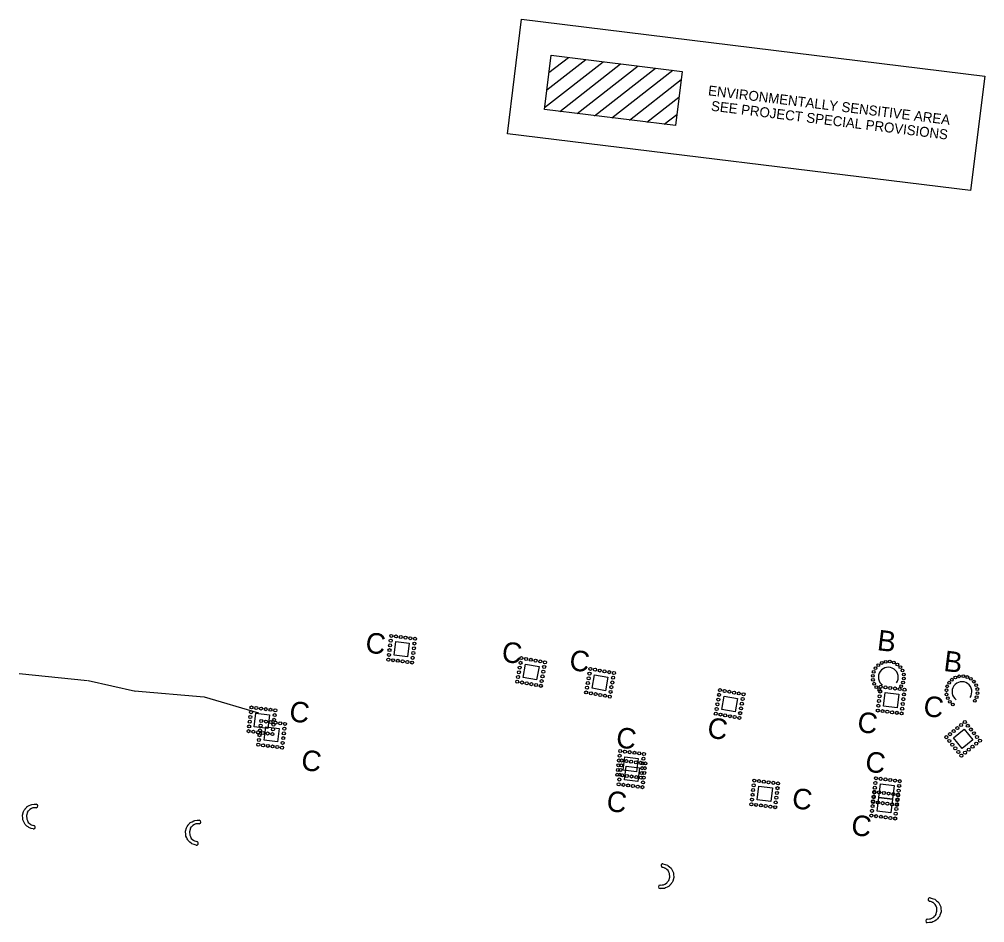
# Model space of a CAD drawing. Extents: x 2470000 to 2520000, y 340000 to 380000.
# Drawn here: x 2481867 to 2482573, y 365982 to 366642 of the extents above; entities that cross this region are included whole.
import ezdxf

# ---------------------------------------------------------------- set-up
doc = ezdxf.new("R2010")
doc.units = 0
for name, color, linetype in [('Environmentally Sensitive Area Note CG CELL', 7, 'Continuous'), ('Label B Final CELL', 7, 'Continuous'), ('Label C CG CELL', 7, 'Continuous'), ('Prop Guardrail', 7, 'Continuous'), ('Prop Guardrail Anchor Unit CELL', 7, 'Continuous'), ('Prop Structure Anchor Unit CELL', 7, 'Continuous'), ('Rock Inlet Sediment Trap Type C CG CELL', 7, 'Continuous'), ('Rock Pipe Inlet Sediment Trap Type B Final CELL', 7, 'Continuous'), ('Scratch_Level_5', 7, 'Continuous'), ('Sheet Data Field CELL', 7, 'Continuous'), ('Wattle Both CELL', 7, 'Continuous')]:
    doc.layers.add(name, color=color, linetype=linetype)

# ---------------------------------------------------------------- blocks, each defined once
blk = doc.blocks.new('C2')
at = {"layer": 'Prop Guardrail Anchor Unit CELL'}
blk.add_text('C', height=0.3, dxfattribs=at).set_placement((-0.161, -0.136))
blk = doc.blocks.new('C3')
at = {"layer": 'Prop Guardrail'}
blk.add_text('C', height=0.3, dxfattribs=at).set_placement((-0.161, -0.136))
blk = doc.blocks.new('B3')
at = {"layer": 'Label B Final CELL'}
blk.add_text('B', height=0.3, dxfattribs=at).set_placement((-0.106, -0.151))
blk = doc.blocks.new('C1')
at = {"layer": 'Label C CG CELL'}
blk.add_text('C', height=0.3, dxfattribs=at).set_placement((-0.161, -0.136))
blk = doc.blocks.new('ESA')
at = {"layer": 'Environmentally Sensitive Area Note CG CELL'}
for p, q in [((-3.41, 0.847), (3.41, 0.847)), ((-3.41, -0.841), (-3.41, 0.847)), ((3.41, 0.847), (3.41, -0.84)), ((-2.919, 0.124), (-2.664, 0.377)), ((-2.919, -0.132), (-2.408, 0.377)), ((-2.919, -0.39), (-2.151, 0.377)), ((-2.919, 0.377), (-0.99, 0.377)), ((-2.919, -0.423), (-2.919, 0.377)), ((-2.693, -0.423), (-1.895, 0.377)), ((-2.437, -0.423), (-1.638, 0.377)), ((-2.18, -0.423), (-1.382, 0.377)), ((-1.924, -0.423), (-1.125, 0.377)), ((-0.99, 0.377), (-0.99, -0.423)), ((-1.667, -0.423), (-0.99, 0.255)), ((-1.411, -0.423), (-0.99, -0.003)), ((-1.154, -0.423), (-0.99, -0.259)), ((-0.99, -0.423), (-2.919, -0.423)), ((3.41, -0.84), (-3.41, -0.841))]:
    blk.add_line(p, q, dxfattribs=at)
for s, p in [('ENVIRONMENTALLY SENSITIVE AREA', (-0.575, 0.076)), ('SEE PROJECT SPECIAL PROVISIONS', (-0.505, -0.142))]:
    blk.add_text(s, height=0.1452, rotation=0.0056, dxfattribs=at).set_placement(p)

msp = doc.modelspace()

# ---------------------------------------------------------------- linework, layer by layer
at = {"layer": 'Prop Structure Anchor Unit CELL'}
for points in [[(2482142.46, 366187.36), (2482152.39, 366186.14), (2482151.17, 366176.22), (2482141.24, 366177.45)], [(2482237.35, 366170.94), (2482247.2, 366169.21), (2482245.46, 366159.36), (2482235.62, 366161.11)], [(2482287.74, 366163.07), (2482297.59, 366161.34), (2482295.85, 366151.49), (2482286, 366153.24)], [(2482382.45, 366147.53), (2482392.3, 366145.8), (2482390.57, 366135.95), (2482380.72, 366137.7)], [(2482040.31, 366135.06), (2482050.23, 366133.84), (2482049.01, 366123.92), (2482039.09, 366125.15)], [(2482550.13, 366116.97), (2482557.89, 366123.27), (2482564.2, 366115.51), (2482556.43, 366109.22)]]:
    msp.add_lwpolyline(points, close=True, dxfattribs=at)
for centre in [(2482138.76, 366188.09), (2482139.19, 366191.56), (2482142.66, 366191.13), (2482146.14, 366190.71), (2482149.61, 366190.28), (2482153.09, 366189.85), (2482156.56, 366189.43), (2482137.91, 366181.14), (2482138.34, 366184.61), (2482155.71, 366182.48), (2482156.13, 366185.95), (2482137.06, 366174.19), (2482137.48, 366177.66), (2482154.85, 366175.53), (2482155.28, 366179), (2482234.31, 366175.31), (2482237.75, 366174.7), (2482241.2, 366174.09), (2482140.53, 366173.76), (2482144, 366173.34), (2482147.48, 366172.91), (2482150.95, 366172.48), (2482154.43, 366172.06), (2482233.09, 366168.41), (2482233.7, 366171.86), (2482244.65, 366173.48), (2482248.09, 366172.88), (2482250.93, 366168.82), (2482251.54, 366172.27), (2482284.69, 366167.44), (2482231.87, 366161.52), (2482232.48, 366164.97), (2482249.72, 366161.93), (2482250.33, 366165.37), (2482283.48, 366160.54), (2482284.08, 366163.99), (2482288.14, 366166.83), (2482291.58, 366166.22), (2482295.03, 366165.61), (2482298.48, 366165.01), (2482301.32, 366160.95), (2482301.93, 366164.4), (2482231.27, 366158.07), (2482234.71, 366157.47), (2482238.16, 366156.86), (2482241.61, 366156.25), (2482245.05, 366155.64), (2482248.5, 366155.03), (2482249.11, 366158.48), (2482282.26, 366153.65), (2482282.87, 366157.1), (2482300.1, 366154.06), (2482300.71, 366157.5), (2482281.65, 366150.2), (2482285.1, 366149.6), (2482288.54, 366148.99), (2482291.99, 366148.38), (2482295.44, 366147.77), (2482298.89, 366147.16), (2482299.49, 366150.61), (2482378.8, 366148.45), (2482379.41, 366151.9), (2482382.85, 366151.29), (2482386.3, 366150.68), (2482389.75, 366150.07), (2482393.2, 366149.47), (2482396.64, 366148.86), (2482037.04, 366139.26), (2482040.51, 366138.83), (2482377.58, 366141.56), (2482378.19, 366145.01), (2482395.43, 366141.96), (2482396.03, 366145.41), (2482036.18, 366132.31), (2482036.61, 366135.79), (2482043.98, 366138.41), (2482047.46, 366137.98), (2482050.93, 366137.55), (2482053.98, 366133.65), (2482054.4, 366137.13), (2482376.37, 366134.66), (2482376.98, 366138.11), (2482379.81, 366134.06), (2482383.26, 366133.45), (2482386.71, 366132.84), (2482390.15, 366132.23), (2482393.6, 366131.62), (2482394.21, 366135.07), (2482394.82, 366138.52), (2482035.33, 366125.36), (2482035.76, 366128.84), (2482053.12, 366126.71), (2482053.55, 366130.18), (2482555.7, 366126.35), (2482558.42, 366128.56), (2482560.62, 366125.84), (2482034.9, 366121.89), (2482038.38, 366121.46), (2482041.85, 366121.04), (2482045.32, 366120.61), (2482048.8, 366120.18), (2482052.27, 366119.76), (2482052.7, 366123.23), (2482544.84, 366117.52), (2482547.55, 366119.73), (2482550.27, 366121.94), (2482552.98, 366124.14), (2482562.83, 366123.13), (2482565.04, 366120.41), (2482567.25, 366117.69), (2482547.04, 366114.81), (2482549.25, 366112.09), (2482564.02, 366110.56), (2482566.74, 366112.77), (2482569.45, 366114.98), (2482551.46, 366109.37), (2482553.67, 366106.66), (2482555.87, 366103.94), (2482558.59, 366106.15), (2482561.31, 366108.36)]:
    msp.add_circle(centre, 1.12, dxfattribs=at)
at = {"layer": 'Rock Inlet Sediment Trap Type C CG CELL'}
for points in [[(2482500.22, 366150.15), (2482510.14, 366148.94), (2482508.92, 366139.01), (2482499, 366140.24)], [(2482407.8, 366081.61), (2482417.73, 366080.4), (2482416.51, 366070.47), (2482406.59, 366071.7)]]:
    msp.add_lwpolyline(points, close=True, dxfattribs=at)
for centre in [(2482496.95, 366154.35), (2482500.42, 366153.93), (2482503.89, 366153.5), (2482507.37, 366153.07), (2482496.09, 366147.4), (2482496.52, 366150.88), (2482510.84, 366152.65), (2482513.89, 366148.74), (2482514.32, 366152.22), (2482495.24, 366140.46), (2482495.67, 366143.93), (2482513.04, 366141.8), (2482513.46, 366145.27), (2482494.81, 366136.98), (2482498.29, 366136.56), (2482501.76, 366136.13), (2482505.23, 366135.7), (2482508.71, 366135.28), (2482512.18, 366134.85), (2482512.61, 366138.32), (2482404.11, 366082.34), (2482404.53, 366085.81), (2482408.01, 366085.39), (2482411.48, 366084.96), (2482414.96, 366084.53), (2482418.43, 366084.11), (2482421.9, 366083.68), (2482403.25, 366075.39), (2482403.68, 366078.87), (2482421.05, 366076.73), (2482421.48, 366080.21), (2482402.4, 366068.44), (2482402.83, 366071.92), (2482420.2, 366069.78), (2482420.62, 366073.26), (2482405.87, 366068.02), (2482409.35, 366067.59), (2482412.82, 366067.16), (2482416.3, 366066.74), (2482419.77, 366066.31)]:
    msp.add_circle(centre, 1.12, dxfattribs=at)
at = {"layer": 'Rock Pipe Inlet Sediment Trap Type B Final CELL'}
for centre in [(2482493.17, 366167.96), (2482495.19, 366170.16), (2482497.71, 366171.75), (2482500.56, 366172.64), (2482503.54, 366172.76), (2482506.45, 366172.11), (2482509.09, 366170.72), (2482511.28, 366168.7), (2482491.13, 366162.41), (2482491.79, 366165.32), (2482512.88, 366166.18), (2482513.77, 366163.34), (2482513.89, 366160.36), (2482551.5, 366161.11), (2482554.35, 366162), (2482557.33, 366162.12), (2482560.24, 366161.47), (2482562.88, 366160.09), (2482491.26, 366159.43), (2482492.15, 366156.59), (2482493.74, 366154.07), (2482511.85, 366154.8), (2482513.24, 366157.45), (2482545.58, 366154.68), (2482546.96, 366157.33), (2482548.98, 366159.52), (2482565.08, 366158.07), (2482566.67, 366155.55), (2482495.93, 366152.04), (2482544.93, 366151.78), (2482545.05, 366148.8), (2482545.94, 366145.95), (2482567.03, 366146.81), (2482567.56, 366152.7), (2482567.68, 366149.72), (2482547.53, 366143.43), (2482549.72, 366141.41), (2482565.64, 366144.17)]:
    msp.add_circle(centre, 1.01, dxfattribs=at)
for centre in [(2482502.51, 366161.38), (2482556.3, 366150.75)]:
    msp.add_arc(centre, 7.26, 324.84296, 234.83414, dxfattribs=at)
at = {"layer": 'Scratch_Level_5'}
for points in [[(2482047.41, 366125.17), (2482057.33, 366123.95), (2482056.12, 366114.02), (2482046.19, 366115.25)], [(2482309.81, 366103.2), (2482319.74, 366101.98), (2482318.52, 366092.05), (2482308.6, 366093.28)], [(2482310.82, 366096.25), (2482320.74, 366095.03), (2482319.52, 366085.1), (2482309.6, 366086.33)], [(2482496.75, 366083.3), (2482506.68, 366082.08), (2482505.46, 366072.16), (2482495.53, 366073.39)], [(2482495.51, 366073.36), (2482505.44, 366072.14), (2482504.22, 366062.21), (2482494.3, 366063.45)]]:
    msp.add_lwpolyline(points, close=True, dxfattribs=at)
for centre in [(2482043.71, 366125.89), (2482044.14, 366129.37), (2482047.61, 366128.94), (2482051.09, 366128.51), (2482054.56, 366128.09), (2482058.03, 366127.66), (2482061.51, 366127.23), (2482042.86, 366118.94), (2482043.29, 366122.42), (2482060.66, 366120.28), (2482061.08, 366123.76), (2482042.01, 366112), (2482042.43, 366115.47), (2482045.48, 366111.57), (2482048.95, 366111.14), (2482052.43, 366110.72), (2482059.8, 366113.34), (2482060.23, 366116.81), (2482055.9, 366110.29), (2482059.38, 366109.86), (2482306.12, 366103.92), (2482306.54, 366107.4), (2482310.02, 366106.97), (2482313.49, 366106.54), (2482316.96, 366106.12), (2482320.44, 366105.69), (2482323.91, 366105.26), (2482305.26, 366096.97), (2482305.69, 366100.45), (2482307.12, 366096.97), (2482307.55, 366100.45), (2482311.02, 366100.02), (2482314.5, 366099.59), (2482317.97, 366099.17), (2482321.44, 366098.74), (2482323.06, 366098.31), (2482323.49, 366101.79), (2482324.92, 366098.31), (2482304.41, 366090.03), (2482304.84, 366093.5), (2482306.27, 366090.02), (2482306.69, 366093.5), (2482307.88, 366089.6), (2482322.21, 366091.37), (2482322.63, 366094.84), (2482324.06, 366091.36), (2482324.49, 366094.84), (2482305.41, 366083.08), (2482305.84, 366086.55), (2482308.89, 366082.65), (2482311.36, 366089.17), (2482312.36, 366082.22), (2482314.83, 366088.75), (2482318.3, 366088.32), (2482321.78, 366087.89), (2482323.21, 366084.42), (2482323.64, 366087.89), (2482493.05, 366084.03), (2482493.48, 366087.5), (2482496.95, 366087.07), (2482500.43, 366086.65), (2482503.9, 366086.22), (2482507.38, 366085.79), (2482510.85, 366085.37), (2482315.84, 366081.8), (2482319.31, 366081.37), (2482322.78, 366080.94), (2482492.2, 366077.08), (2482492.24, 366077.56), (2482492.63, 366080.55), (2482495.72, 366077.13), (2482499.19, 366076.7), (2482502.66, 366076.28), (2482506.14, 366075.85), (2482509.61, 366075.42), (2482510, 366078.42), (2482510.42, 366081.89), (2482491.35, 366070.13), (2482491.39, 366070.61), (2482491.77, 366073.6), (2482491.82, 366074.08), (2482494.82, 366069.7), (2482498.3, 366069.28), (2482501.77, 366068.85), (2482505.24, 366068.42), (2482508.76, 366068.48), (2482509.14, 366071.47), (2482509.19, 366071.95), (2482509.57, 366074.95), (2482490.54, 366063.66), (2482490.96, 366067.13), (2482507.91, 366061.53), (2482508.33, 366065), (2482508.72, 366068), (2482490.11, 366060.19), (2482493.58, 366059.76), (2482497.06, 366059.33), (2482500.53, 366058.91), (2482504, 366058.48), (2482507.48, 366058.05)]:
    msp.add_circle(centre, 1.12, dxfattribs=at)
at = {"layer": 'Sheet Data Field CELL'}
for p, q in [((2481867.32, 366164.17), (2481917.06, 366159.05)), ((2481917.64, 366158.95), (2481952.27, 366151.18)), ((2481951.59, 366151.29), (2482002.52, 366146.99)), ((2482002.52, 366146.99), (2482042.09, 366135.36))]:
    msp.add_line(p, q, dxfattribs=at)
at = {"layer": 'Wattle Both CELL'}
for p, q in [((2481873.41, 366062.71), (2481872.63, 366060.2)), ((2481873.41, 366062.71), (2481874.15, 366063.64)), ((2481874.85, 366064.51), (2481874.15, 366063.64)), ((2481874.85, 366064.51), (2481875, 366064.69)), ((2481876.3, 366065.34), (2481875, 366064.69)), ((2481877.29, 366065.83), (2481876.3, 366065.34)), ((2481878.08, 366065.87), (2481877.29, 366065.83)), ((2481879.63, 366065.96), (2481878.08, 366065.87)), ((2481872.63, 366060.19), (2481872.63, 366060.2)), ((2481872.63, 366060.19), (2481872.75, 366057.65)), ((2481872.75, 366057.65), (2481873.25, 366056.56)), ((2481873.25, 366056.56), (2481873.86, 366055.25)), ((2481873.86, 366055.25), (2481874.65, 366054.59)), ((2481874.65, 366054.59), (2481875.79, 366053.64)), ((2481876.11, 366053.54), (2481875.79, 366053.64)), ((2481876.11, 366053.54), (2481877.88, 366052.97)), ((2481992.56, 366050.94), (2481991.78, 366048.43)), ((2481991.78, 366048.42), (2481991.78, 366048.43)), ((2481991.78, 366048.42), (2481991.9, 366045.88)), ((2481992.56, 366050.94), (2481993.3, 366051.87)), ((2481994, 366052.73), (2481993.3, 366051.87)), ((2481994, 366052.73), (2481994.15, 366052.92)), ((2481995.45, 366053.56), (2481994.15, 366052.92)), ((2481996.44, 366054.06), (2481995.45, 366053.56)), ((2481997.23, 366054.1), (2481996.44, 366054.06)), ((2481998.78, 366054.19), (2481997.23, 366054.1)), ((2481991.9, 366045.88), (2481992.4, 366044.78)), ((2481992.4, 366044.78), (2481993.01, 366043.47)), ((2481993.01, 366043.47), (2481993.8, 366042.82)), ((2481993.8, 366042.82), (2481994.94, 366041.87)), ((2481995.26, 366041.77), (2481994.94, 366041.87)), ((2481995.26, 366041.77), (2481997.03, 366041.2)), ((2482339.26, 366021.85), (2482337.48, 366022.42)), ((2482339.26, 366021.85), (2482339.57, 366021.75)), ((2482340.71, 366020.8), (2482339.57, 366021.75)), ((2482341.5, 366020.14), (2482340.71, 366020.8)), ((2482342.11, 366018.83), (2482341.5, 366020.14)), ((2482341.96, 366012.67), (2482342.73, 366015.19)), ((2482342.61, 366017.74), (2482342.11, 366018.83)), ((2482342.73, 366015.2), (2482342.61, 366017.74)), ((2482342.73, 366015.2), (2482342.73, 366015.19)), ((2482335.74, 366009.43), (2482337.29, 366009.51)), ((2482337.29, 366009.51), (2482338.08, 366009.56)), ((2482338.08, 366009.56), (2482339.06, 366010.05)), ((2482339.06, 366010.05), (2482340.36, 366010.7)), ((2482340.51, 366010.88), (2482340.36, 366010.7)), ((2482340.51, 366010.88), (2482341.21, 366011.75)), ((2482341.96, 366012.67), (2482341.21, 366011.75)), ((2482534.6, 365996.96), (2482532.83, 365997.53)), ((2482534.6, 365996.96), (2482534.92, 365996.86)), ((2482536.05, 365995.92), (2482534.92, 365996.86)), ((2482536.84, 365995.26), (2482536.05, 365995.92)), ((2482537.45, 365993.95), (2482536.84, 365995.26)), ((2482537.96, 365992.85), (2482537.45, 365993.95)), ((2482538.07, 365990.32), (2482537.96, 365992.85)), ((2482531.08, 365984.55), (2482532.63, 365984.63)), ((2482532.63, 365984.63), (2482533.42, 365984.68)), ((2482533.42, 365984.68), (2482534.41, 365985.17)), ((2482534.41, 365985.17), (2482535.71, 365985.81)), ((2482535.85, 365986), (2482535.71, 365985.81)), ((2482535.85, 365986), (2482536.55, 365986.86)), ((2482537.3, 365987.79), (2482536.55, 365986.86)), ((2482537.3, 365987.79), (2482538.07, 365990.3)), ((2482538.07, 365990.32), (2482538.07, 365990.3))]:
    msp.add_line(p, q, dxfattribs=at)
for points in [[(2481877.56, 366050.39), (2481876.07, 366050.85), (2481874.33, 366051.38), (2481873.69, 366051.91), (2481872.91, 366052.55), (2481871.53, 366053.7), (2481871.51, 366053.73), (2481871.31, 366054.13), (2481871.28, 366054.19), (2481870.86, 366055.05), (2481870.56, 366055.65), (2481869.92, 366056.97), (2481869.85, 366058.01), (2481869.68, 366060.55), (2481869.68, 366060.56), (2481870.49, 366063.07), (2481870.8, 366064.05), (2481871.54, 366064.91), (2481871.69, 366065.09), (2481872.32, 366065.83), (2481872.79, 366066.38), (2481872.91, 366066.51), (2481873.14, 366066.79), (2481873.15, 366066.79), (2481874.51, 366067.45), (2481875.72, 366068.04), (2481876.45, 366068.39), (2481878.2, 366068.51), (2481879.75, 366068.62)], [(2481996.71, 366038.62), (2481995.22, 366039.08), (2481993.48, 366039.6), (2481992.84, 366040.13), (2481992.06, 366040.78), (2481990.68, 366041.92), (2481990.66, 366041.96), (2481990.46, 366042.36), (2481990.43, 366042.42), (2481990.01, 366043.28), (2481989.71, 366043.88), (2481989.07, 366045.19), (2481989, 366046.23), (2481988.83, 366048.78), (2481988.83, 366048.79), (2481989.64, 366051.3), (2481989.95, 366052.28), (2481990.69, 366053.14), (2481990.84, 366053.32), (2481991.47, 366054.05), (2481991.94, 366054.61), (2481992.06, 366054.74), (2481992.29, 366055.02), (2481992.3, 366055.02), (2481993.66, 366055.68), (2481994.87, 366056.26), (2481995.6, 366056.61), (2481997.35, 366056.74), (2481998.9, 366056.85)], [(2482337.8, 366024.99), (2482339.29, 366024.54), (2482341.03, 366024.01), (2482341.67, 366023.48), (2482342.45, 366022.84), (2482343.84, 366021.69), (2482343.85, 366021.66), (2482344.05, 366021.26), (2482344.08, 366021.19), (2482344.5, 366020.34), (2482344.8, 366019.74), (2482345.44, 366018.42), (2482345.51, 366017.38), (2482345.68, 366014.84), (2482345.68, 366014.83), (2482344.87, 366012.32), (2482344.56, 366011.34), (2482343.82, 366010.48), (2482343.67, 366010.29), (2482343.04, 366009.56), (2482342.57, 366009.01), (2482342.45, 366008.88), (2482342.22, 366008.6), (2482342.21, 366008.6), (2482340.85, 366007.94), (2482339.64, 366007.35), (2482338.91, 366007), (2482337.16, 366006.88), (2482335.62, 366006.77)], [(2482533.14, 366000.11), (2482534.63, 365999.66), (2482536.37, 365999.13), (2482537.02, 365998.6), (2482537.8, 365997.95), (2482539.18, 365996.81), (2482539.2, 365996.77), (2482539.39, 365996.38), (2482539.43, 365996.31), (2482539.85, 365995.45), (2482540.14, 365994.85), (2482540.79, 365993.54), (2482540.86, 365992.5), (2482541.02, 365989.95), (2482541.02, 365989.94), (2482540.21, 365987.43), (2482539.9, 365986.45), (2482539.16, 365985.59), (2482539.01, 365985.41), (2482538.39, 365984.68), (2482537.91, 365984.12), (2482537.8, 365984), (2482537.56, 365983.72), (2482537.55, 365983.71), (2482536.19, 365983.05), (2482534.99, 365982.47), (2482534.26, 365982.12), (2482532.5, 365981.99), (2482530.96, 365981.89)]]:
    msp.add_lwpolyline(points, dxfattribs=at)
for centre, radius, start, end in [((2481879.58, 366067.29), 1.33, 271.88966, 83.0023), ((2481998.73, 366055.52), 1.33, 271.88966, 83.0023), ((2481877.72, 366051.68), 1.3, 263.0023, 83.0023), ((2481996.87, 366039.91), 1.3, 263.0023, 83.0023), ((2482337.64, 366023.71), 1.3, 83.0023, 263.0023), ((2482335.78, 366008.1), 1.33, 91.88966, 263.0023), ((2482532.98, 365998.82), 1.3, 83.0023, 263.0023), ((2482531.12, 365983.21), 1.33, 91.88966, 263.0023)]:
    msp.add_arc(centre, radius, start, end, dxfattribs=at)

# ---------------------------------------------------------------- block references
at = {"layer": 'Environmentally Sensitive Area Note CG CELL', "xscale": 50.00000000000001, "yscale": 49.99999999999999, "rotation": -6.997703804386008}
msp.add_blockref('ESA', (2482398.54, 366579.51), dxfattribs=at)
at = {"layer": 'Label B Final CELL', "xscale": 50, "yscale": 50, "rotation": -6.997703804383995}
for p in [(2482499.98, 366188.05), (2482548.6, 366172.86)]:
    msp.add_blockref('B3', p, dxfattribs=at)
at = {"layer": 'Label C CG CELL', "xscale": 49.99999999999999, "yscale": 50.00000000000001, "rotation": -6.997703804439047}
for p in [(2482488.1, 366127.24), (2482440.35, 366071.5)]:
    msp.add_blockref('C1', p, dxfattribs=at)
at = {"layer": 'Prop Structure Anchor Unit CELL'}
for name, p, xscale, yscale, rotation in [('C2', (2482128.52, 366185.3), 49.99999999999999, 50.00000000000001, -6.997703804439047), ('C2', (2482228.19, 366178.51), 49.99999999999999, 50.00000000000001, -6.997703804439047), ('C2', (2482277.62, 366172.44), 49.99999999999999, 50.00000000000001, -6.997703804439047), ('C2', (2482072.89, 366135.06), 49.99999999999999, 50.00000000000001, -6.997703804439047), ('C2', (2482378.49, 366122.97), 50.00000000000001, 49.99999999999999, -6.997703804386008), ('C3', (2482081.61, 366099.44), 50.00000000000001, 49.99999999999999, -6.997703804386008)]:
    msp.add_blockref(name, p, dxfattribs=dict(at, xscale=xscale, yscale=yscale, rotation=rotation))
at = {"layer": 'Rock Inlet Sediment Trap Type C CG CELL', "xscale": 50.00000000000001, "yscale": 49.99999999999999, "rotation": -6.997703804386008}
msp.add_blockref('C2', (2482536.35, 366138.94), dxfattribs=at)
at = {"layer": 'Scratch_Level_5', "xscale": 49.99999999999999, "yscale": 50.00000000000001, "rotation": -6.997703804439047}
for p in [(2482311.74, 366115.95), (2482493.88, 366098.27), (2482304.74, 366069.48), (2482483.6, 366051.93)]:
    msp.add_blockref('C3', p, dxfattribs=at)

doc.saveas('drawing.dxf')
